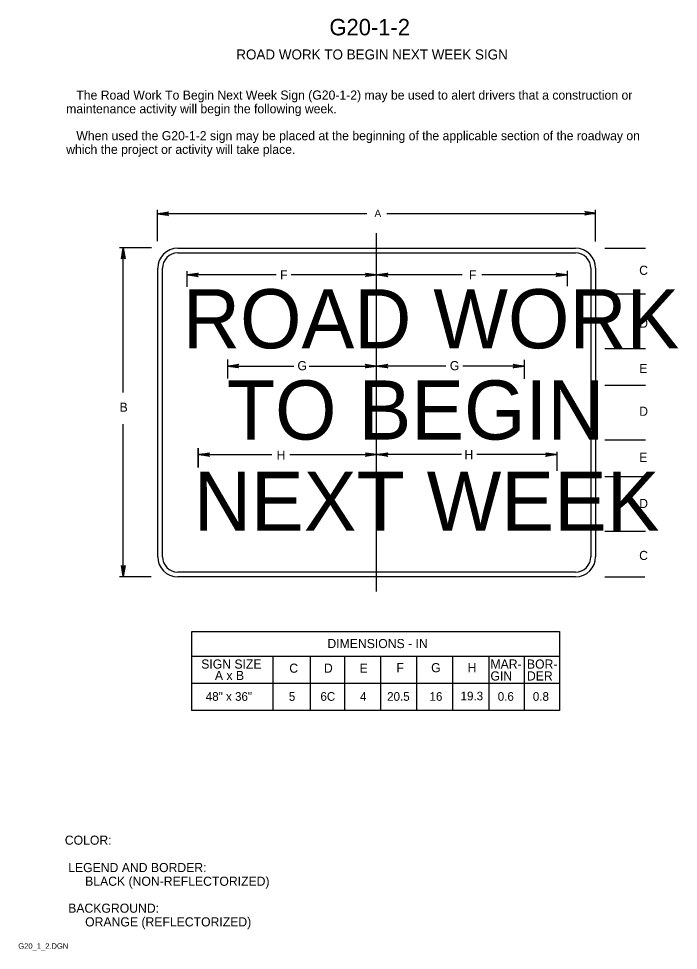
# Model space of a CAD drawing. Extents: x 0.012 to 0.193, y 0.004 to 0.259.
import ezdxf

# ---------------------------------------------------------------- set-up
doc = ezdxf.new("R2010")
doc.units = 0
for name, color, linetype in [('1', 7, 'Continuous'), ('2', 7, 'Continuous'), ('3', 7, 'Continuous'), ('4', 7, 'Continuous'), ('5', 7, 'Continuous')]:
    doc.layers.add(name, color=color, linetype=linetype)

# ---------------------------------------------------------------- blocks, each defined once
blk = doc.blocks.new('RARROW')
at = {"layer": '3'}
for p, q in [((-2.156, 0.285), (-2.2665, 0.384625)), ((-2.2665, 0.384625), (0, 0)), ((0, 0), (-2.2665, -0.379125)), ((-2.156, 0.285), (-2.075625, 0.12075)), ((0, 0), (-2.156, 0.285)), ((-2.14975, -0.2705), (0, 0)), ((-2.075625, 0.12075), (0, 0)), ((0, 0), (-2.074, -0.108)), ((-2.2665, -0.379125), (-2.14975, -0.2705)), ((-2.074, -0.108), (-2.14975, -0.2705))]:
    blk.add_line(p, q, dxfattribs=at)

msp = doc.modelspace()

# ---------------------------------------------------------------- linework, layer by layer
at = {"layer": '1'}
for p, q in [((0.16063, 0.09129), (0.16063, 0.06966)), ((0.14126, 0.08441), (0.14126, 0.06966)), ((0.15101, 0.08441), (0.15101, 0.06966))]:
    msp.add_line(p, q, dxfattribs=at)
at = {"layer": '2'}
for p, q in [((0.05988, 0.09129), (0.16063, 0.09129)), ((0.05988, 0.09125), (0.05988, 0.06963)), ((0.16063, 0.08441), (0.05988, 0.08441)), ((0.08213, 0.08441), (0.08213, 0.06966)), ((0.09237, 0.08438), (0.09237, 0.06963)), ((0.10175, 0.08438), (0.10175, 0.06963)), ((0.11163, 0.08438), (0.11163, 0.06963)), ((0.1215, 0.08438), (0.1215, 0.06963)), ((0.13137, 0.08438), (0.13137, 0.06963)), ((0.16063, 0.07704), (0.05988, 0.07704)), ((0.16063, 0.06966), (0.05988, 0.06966))]:
    msp.add_line(p, q, dxfattribs=at)
at = {"layer": '3'}
for p, q in [((0.05049, 0.19827), (0.05049, 0.20677)), ((0.17057, 0.19817), (0.17057, 0.20679)), ((0.10792, 0.20575), (0.0505, 0.20575)), ((0.11335, 0.20579), (0.17057, 0.20579)), ((0.04884, 0.19638), (0.04009, 0.19638)), ((0.04113, 0.15679), (0.04113, 0.19637)), ((0.05607, 0.19499), (0.16507, 0.19499)), ((0.17307, 0.19629), (0.18419, 0.19629)), ((0.05187, 0.11179), (0.05187, 0.19079)), ((0.05862, 0.18575), (0.05862, 0.19002)), ((0.083, 0.189), (0.05863, 0.189)), ((0.11057, 0.189), (0.08713, 0.189)), ((0.11057, 0.18792), (0.11057, 0.19004)), ((0.13401, 0.189), (0.11057, 0.189)), ((0.16284, 0.189), (0.1394, 0.189)), ((0.16284, 0.18588), (0.16284, 0.19008)), ((0.16927, 0.19079), (0.16927, 0.11179)), ((0.17307, 0.18379), (0.18419, 0.18379)), ((0.17307, 0.16879), (0.18419, 0.16879)), ((0.06975, 0.16058), (0.06975, 0.16583)), ((0.06975, 0.164), (0.08785, 0.164)), ((0.09212, 0.164), (0.11057, 0.164)), ((0.1295, 0.164), (0.11057, 0.164)), ((0.15107, 0.164), (0.13416, 0.164)), ((0.15107, 0.16047), (0.15107, 0.16572)), ((0.17307, 0.15879), (0.18419, 0.15879)), ((0.04107, 0.14813), (0.04107, 0.10629)), ((0.17307, 0.14379), (0.18419, 0.14379)), ((0.06169, 0.14149), (0.06169, 0.13624)), ((0.06169, 0.13624), (0.06169, 0.14149)), ((0.1599, 0.14056), (0.1599, 0.13531)), ((0.06169, 0.13975), (0.08188, 0.13975)), ((0.08675, 0.13975), (0.11057, 0.13975)), ((0.13384, 0.13975), (0.11057, 0.13975)), ((0.1599, 0.13975), (0.138, 0.13975)), ((0.17307, 0.13379), (0.18419, 0.13379)), ((0.17307, 0.11879), (0.18419, 0.11879)), ((0.16507, 0.10759), (0.05607, 0.10759)), ((0.04882, 0.10629), (0.04007, 0.10629)), ((0.17307, 0.10629), (0.18407, 0.10629))]:
    msp.add_line(p, q, dxfattribs=at)
for centre, start, end in [((0.05607, 0.19079), 90, 180), ((0.16507, 0.19079), 0, 90), ((0.05607, 0.11179), 180, 270), ((0.16507, 0.11179), 270, 0)]:
    msp.add_arc(centre, 0.0042, start, end, dxfattribs=at)
at = {"layer": '4'}
msp.add_line((0.11057, 0.10221), (0.11057, 0.20038), dxfattribs=at)
at = {"layer": '5'}
for p, q in [((0.05607, 0.19629), (0.16507, 0.19629)), ((0.05057, 0.11179), (0.05057, 0.19079)), ((0.17057, 0.19079), (0.17057, 0.11179)), ((0.16507, 0.10629), (0.05607, 0.10629))]:
    msp.add_line(p, q, dxfattribs=at)
for centre, start, end in [((0.05607, 0.19079), 90, 180), ((0.16507, 0.19079), 0, 90), ((0.05607, 0.11179), 180, 270), ((0.16507, 0.11179), 270, 0)]:
    msp.add_arc(centre, 0.0055, start, end, dxfattribs=at)

# ---------------------------------------------------------------- block references
at = {"layer": '3', "xscale": 0.0013236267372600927, "yscale": 0.001309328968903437}
for p, rotation in [((0.0505, 0.20575), 180), ((0.04113, 0.19637), 90), ((0.05863, 0.189), 180), ((0.11063, 0.189), 180), ((0.06975, 0.164), 180), ((0.11063, 0.164), 180), ((0.06175, 0.13975), 180), ((0.11063, 0.13975), 180), ((0.04113, 0.10637), -90)]:
    msp.add_blockref('RARROW', p, dxfattribs=dict(at, rotation=rotation))
for p in [(0.17062, 0.20588), (0.1105, 0.189), (0.16275, 0.189), (0.1105, 0.164), (0.151, 0.164), (0.1105, 0.13975), (0.15988, 0.13975)]:
    msp.add_blockref('RARROW', p, dxfattribs=at)

# ---------------------------------------------------------------- texts
at = {"layer": '1'}
for s, height, p in [('G20-1-2', 0.0045, (0.09763, 0.25462)), ('ROAD WORK TO BEGIN NEXT WEEK SIGN', 0.0027503, (0.07212, 0.248)), ('TO BEGIN', 0.016198, (0.0695, 0.14388)), ('NEXT WEEK', 0.016198, (0.0605, 0.11888)), ('MAR-', 0.0025, (0.14175, 0.08113)), ('BOR-', 0.0025, (0.15175, 0.08113)), ('GIN', 0.0025, (0.14175, 0.07787)), ('DER', 0.0025, (0.15175, 0.07787)), ('COLOR:', 0.0025, (0.02513, 0.03288)), (' LEGEND AND BORDER:', 0.0024998, (0.02513, 0.02538)), ('      BLACK (NON-REFLECTORIZED)', 0.0024998, (0.02513, 0.02163)), (' BACKGROUND:', 0.0024998, (0.02513, 0.01425)), ('      ORANGE (REFLECTORIZED)', 0.0024998, (0.02513, 0.0105)), ('G20_1_2.DGN', 0.0015, (0.01238, 0.00438))]:
    msp.add_text(s, height=height, dxfattribs=at).set_placement(p)
at = {"layer": '2'}
for s, height, p in [('   The Road Work To Begin Next Week Sign (G20-1-2) may be used to alert drivers that a construction or', 0.00249975, (0.0255, 0.237)), ('maintenance activity will begin the following week.', 0.0024998, (0.0255, 0.23325)), ('   When used the G20-1-2 sign may be placed at the beginning of the applicable section of the roadway on', 0.00249975, (0.0255, 0.22587)), ('which the project or activity will take place.', 0.0024998, (0.0255, 0.22213)), ('DIMENSIONS - IN', 0.0024998, (0.09708, 0.08675)), ('SIGN SIZE', 0.0025, (0.0625, 0.08113)), ('C', 0.0025, (0.08663, 0.08)), ('D', 0.0025, (0.09613, 0.08)), ('E', 0.0025, (0.10587, 0.08)), ('F', 0.0025, (0.116, 0.08013)), ('G', 0.0025, (0.1255, 0.08013)), ('H', 0.0025, (0.1355, 0.08013)), ('A x B', 0.0025, (0.06625, 0.078))]:
    msp.add_text(s, height=height, dxfattribs=at).set_placement(p)
at = {"layer": '3'}
for s, height, p in [('A', 0.002, (0.11, 0.20488)), ('C', 0.0025, (0.1825, 0.189)), ('F', 0.0025, (0.08413, 0.18775)), ('F', 0.0025, (0.13587, 0.18775)), ('D', 0.0025, (0.1825, 0.1745)), ('G', 0.0025, (0.08887, 0.16287)), ('G', 0.0025, (0.13062, 0.16287)), ('E', 0.0025, (0.1825, 0.16212)), ('B', 0.0025, (0.04013, 0.1515)), ('D', 0.0025, (0.1825, 0.15038)), ('H', 0.0025, (0.08313, 0.13837)), ('H', 0.0025, (0.13462, 0.1385)), ('E', 0.0025, (0.1825, 0.13775)), ('D', 0.0025, (0.1825, 0.12513)), ('C', 0.0025, (0.1825, 0.11088)), ('48" x 36"', 0.002375, (0.06375, 0.07231)), ('5', 0.00238, (0.08652, 0.07231)), ('6C', 0.002375, (0.09516, 0.07231)), ('4', 0.00238, (0.10601, 0.07231)), ('20.5', 0.002375, (0.11344, 0.07231)), ('16', 0.002375, (0.12505, 0.07231)), ('19.3', 0.002375, (0.13356, 0.07244)), ('0.6', 0.002375, (0.14374, 0.07231)), ('0.8', 0.002375, (0.15336, 0.07231))]:
    msp.add_text(s, height=height, dxfattribs=at).set_placement(p)
at = {"layer": '4'}
msp.add_text('ROAD WORK', height=0.016198, dxfattribs=at).set_placement((0.0575, 0.16887))

doc.saveas('drawing.dxf')
